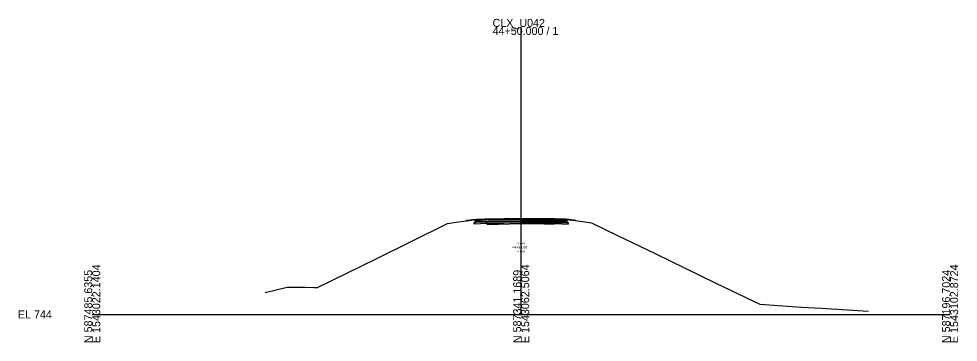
# Model space of a CAD drawing. Extents: x -26 to 1603, y -10 to 5557.
# Drawn here: x -25.7 to 302.8, y 990.3 to 1103.4 of the extents above; entities that cross this region are included whole.
import ezdxf

# ---------------------------------------------------------------- set-up
doc = ezdxf.new("R2010")
doc.units = 0
for name, color, linetype in [('GK_Cells', 7, 'Continuous'), ('XS_P_Annotation', 7, 'Continuous'), ('XS_P_Earthwork_Shapes', 7, 'Continuous'), ('XS_P_Finished_Grade', 7, 'Continuous'), ('XS_P_Pavt_Layers', 7, 'Continuous'), ('XS_P_Pavt_Surface', 7, 'Continuous'), ('XS_P_Shoulder_Layers', 7, 'Continuous'), ('XS_P_Shoulder_Surface', 7, 'Continuous'), ('XS_P_Subgrade', 7, 'Continuous'), ('XS_X_Ground_Line', 7, 'Continuous'), ('XS_X_Pavt', 7, 'Continuous')]:
    doc.layers.add(name, color=color, linetype=linetype)

msp = doc.modelspace()

# ---------------------------------------------------------------- linework, layer by layer
at = {"layer": 'GK_Cells'}
for p, q in [((150, 1000), (150, 1100.52)), ((0, 1000), (150, 1000)), ((150, 1000), (300, 1000))]:
    msp.add_line(p, q, dxfattribs=at)
at = {"layer": 'XS_P_Earthwork_Shapes'}
for points in [[(131, 1032.89), (130.63, 1032.7), (133.61, 1033.1)], [(131, 1032.89), (130.63, 1032.7), (133.61, 1033.1)], [(131, 1032.89), (130.63, 1032.7), (133.61, 1033.1)], [(131, 1032.89), (130.63, 1032.7), (133.61, 1033.1)], [(137.94, 1031.79), (133.58, 1031.61), (133.58, 1032.11), (134.08, 1032.13), (134.08, 1032.89), (134.41, 1032.9), (134.41, 1033.17), (133.61, 1033.1), (134.46, 1033.22), (134.54, 1033.22), (134.54, 1032.47), (137.21, 1032.53), (137.94, 1032.55)], [(137.94, 1031.79), (133.58, 1031.61), (133.58, 1032.11), (134.08, 1032.13), (134.08, 1032.89), (134.41, 1032.9), (134.41, 1033.17), (133.61, 1033.1), (134.46, 1033.22), (134.54, 1033.22), (134.54, 1032.47), (137.21, 1032.53), (137.94, 1032.55)], [(137.94, 1031.79), (133.58, 1031.61), (133.58, 1032.11), (134.08, 1032.13), (134.08, 1032.89), (134.41, 1032.9), (134.41, 1033.17), (133.61, 1033.1), (134.46, 1033.22), (134.54, 1033.22), (134.54, 1032.47), (137.21, 1032.53), (137.94, 1032.55)], [(137.94, 1031.79), (133.58, 1031.61), (133.58, 1032.11), (134.08, 1032.13), (134.08, 1032.89), (134.41, 1032.9), (134.41, 1033.17), (133.61, 1033.1), (134.46, 1033.22), (134.54, 1033.22), (134.54, 1032.47), (137.21, 1032.53), (137.94, 1032.55)], [(134.54, 1033.22), (137.21, 1033.28), (138.45, 1033.31), (142.04, 1033.37), (149.93, 1033.51), (158.15, 1033.42), (161.66, 1033.38), (164.55, 1033.33), (165.48, 1033.32), (165.48, 1032.57), (164.55, 1032.58), (161.66, 1032.63), (161.49, 1032.63), (158.15, 1032.67), (149.93, 1032.76), (142.04, 1032.62), (138.45, 1032.56), (137.94, 1032.55), (137.21, 1032.53), (134.54, 1032.47)], [(134.54, 1033.22), (137.21, 1033.28), (138.45, 1033.31), (142.04, 1033.37), (149.93, 1033.51), (158.15, 1033.42), (161.66, 1033.38), (164.55, 1033.33), (165.48, 1033.32), (165.48, 1032.57), (164.55, 1032.58), (161.66, 1032.63), (161.49, 1032.63), (158.15, 1032.67), (149.93, 1032.76), (142.04, 1032.62), (138.45, 1032.56), (137.94, 1032.55), (137.21, 1032.53), (134.54, 1032.47)], [(158.15, 1032.67), (161.49, 1032.63), (161.66, 1032.63), (164.55, 1032.58), (165.48, 1032.57), (165.48, 1033.32), (164.55, 1033.33), (161.66, 1033.38), (158.15, 1033.42), (149.93, 1033.51), (142.04, 1033.37), (138.45, 1033.31), (137.21, 1033.28), (134.54, 1033.22), (134.54, 1032.47), (137.21, 1032.53), (137.94, 1032.55), (138.45, 1032.56), (142.04, 1032.62), (149.93, 1032.76)], [(134.54, 1033.22), (137.21, 1033.28), (138.45, 1033.31), (142.04, 1033.37), (149.93, 1033.51), (158.15, 1033.42), (161.66, 1033.38), (164.55, 1033.33), (165.48, 1033.32), (165.48, 1032.57), (164.55, 1032.58), (161.66, 1032.63), (161.49, 1032.63), (158.15, 1032.67), (149.93, 1032.76), (142.04, 1032.62), (138.45, 1032.56), (137.94, 1032.55), (137.21, 1032.53), (134.54, 1032.47)], [(161.49, 1031.8), (150, 1031.98), (138.04, 1031.79), (137.94, 1031.79), (137.94, 1032.55), (138.45, 1032.56), (142.04, 1032.62), (149.93, 1032.76), (158.15, 1032.67), (161.49, 1032.63)], [(158.15, 1032.67), (161.49, 1032.63), (161.49, 1031.8), (150, 1031.98), (138.04, 1031.79), (137.94, 1031.79), (137.94, 1032.55), (138.45, 1032.56), (142.04, 1032.62), (149.93, 1032.76)], [(158.15, 1032.67), (161.49, 1032.63), (161.49, 1031.8), (150, 1031.98), (138.04, 1031.79), (137.94, 1031.79), (137.94, 1032.55), (138.45, 1032.56), (142.04, 1032.62), (149.93, 1032.76)], [(161.49, 1031.8), (150, 1031.98), (138.04, 1031.79), (137.94, 1031.79), (137.94, 1032.55), (138.45, 1032.56), (142.04, 1032.62), (149.93, 1032.76), (158.15, 1032.67), (161.49, 1032.63)], [(165.59, 1033.17), (168.42, 1032.93), (165.68, 1033.31), (165.48, 1033.32), (165.48, 1032.57), (164.55, 1032.58), (161.66, 1032.63), (161.49, 1032.63), (161.49, 1031.8), (161.96, 1031.79), (166.42, 1031.61), (166.42, 1032.11), (165.92, 1032.13), (165.92, 1032.89), (165.59, 1032.9)], [(165.48, 1033.32), (165.68, 1033.31), (168.42, 1032.93), (165.59, 1033.17), (165.59, 1032.9), (165.92, 1032.89), (165.92, 1032.13), (166.42, 1032.11), (166.42, 1031.61), (161.96, 1031.79), (161.49, 1031.8), (161.49, 1032.63), (161.66, 1032.63), (164.55, 1032.58), (165.48, 1032.57)], [(165.59, 1033.17), (168.42, 1032.93), (165.68, 1033.31), (165.48, 1033.32), (165.48, 1032.57), (164.55, 1032.58), (161.66, 1032.63), (161.49, 1032.63), (161.49, 1031.8), (161.96, 1031.79), (166.42, 1031.61), (166.42, 1032.11), (165.92, 1032.13), (165.92, 1032.89), (165.59, 1032.9)], [(165.48, 1033.32), (165.68, 1033.31), (168.42, 1032.93), (165.59, 1033.17), (165.59, 1032.9), (165.92, 1032.89), (165.92, 1032.13), (166.42, 1032.11), (166.42, 1031.61), (161.96, 1031.79), (161.49, 1031.8), (161.49, 1032.63), (161.66, 1032.63), (164.55, 1032.58), (165.48, 1032.57)], [(169, 1032.89), (169.09, 1032.84), (168.42, 1032.93)], [(169, 1032.89), (169.09, 1032.84), (168.42, 1032.93)], [(169, 1032.89), (169.09, 1032.84), (168.42, 1032.93)], [(169, 1032.89), (169.09, 1032.84), (168.42, 1032.93)]]:
    msp.add_lwpolyline(points, close=True, dxfattribs=at)
at = {"layer": 'XS_P_Finished_Grade'}
for p, q in [((131, 1032.89), (130.63, 1032.7)), ((134.41, 1033.17), (131, 1032.89)), ((165.59, 1033.17), (169, 1032.89)), ((169, 1032.89), (169.09, 1032.84))]:
    msp.add_line(p, q, dxfattribs=at)
at = {"layer": 'XS_P_Pavt_Layers'}
for p, q in [((133.58, 1032.11), (133.58, 1031.61)), ((134.08, 1032.89), (134.08, 1032.13)), ((134.41, 1033.17), (134.41, 1032.9)), ((150, 1033.38), (138, 1033.19)), ((150, 1033.23), (138, 1033.04)), ((150.02, 1032.48), (138.02, 1032.29)), ((150.02, 1031.98), (138.02, 1031.79)), ((149.98, 1032.48), (161.98, 1032.29)), ((149.98, 1031.98), (161.98, 1031.79)), ((150, 1033.38), (162, 1033.19)), ((150, 1033.23), (162, 1033.04)), ((165.59, 1033.17), (165.59, 1032.9)), ((165.92, 1032.89), (165.92, 1032.13)), ((166.42, 1032.11), (166.42, 1031.61))]:
    msp.add_line(p, q, dxfattribs=at)
at = {"layer": 'XS_P_Pavt_Surface'}
for q in [(138, 1033.31), (162, 1033.31)]:
    msp.add_line((150, 1033.5), q, dxfattribs=at)
at = {"layer": 'XS_P_Shoulder_Layers'}
for p, q in [((138.04, 1032.29), (133.58, 1032.11)), ((138.06, 1031.79), (133.58, 1031.61)), ((138.01, 1033.04), (134.08, 1032.89)), ((138, 1033.19), (134.42, 1033.04)), ((161.94, 1031.79), (166.42, 1031.61)), ((161.96, 1032.29), (166.42, 1032.11)), ((161.99, 1033.04), (165.92, 1032.89)), ((162, 1033.19), (165.58, 1033.04))]:
    msp.add_line(p, q, dxfattribs=at)
at = {"layer": 'XS_P_Shoulder_Surface'}
for p, q in [((138, 1033.31), (134.41, 1033.17)), ((162, 1033.31), (165.59, 1033.17))]:
    msp.add_line(p, q, dxfattribs=at)
at = {"layer": 'XS_P_Subgrade'}
msp.add_lwpolyline([(165.59, 1033.17), (165.59, 1032.9), (165.92, 1032.89), (165.92, 1032.13), (166.42, 1032.11), (166.42, 1031.61), (161.96, 1031.79), (150, 1031.98), (138.04, 1031.79), (133.58, 1031.61), (133.58, 1032.11), (134.08, 1032.13), (134.08, 1032.89), (134.41, 1032.9), (134.41, 1033.17)], dxfattribs=at)
at = {"layer": 'XS_X_Ground_Line'}
msp.add_lwpolyline([(60.47, 1007.73), (68.18, 1009.52), (73.06, 1009.6), (74.41, 1009.55), (77.48, 1009.43), (78.81, 1009.38), (99.25, 1019.49), (124.19, 1031.82), (127.23, 1032.24), (134.46, 1033.22), (137.21, 1033.28), (138.45, 1033.31), (142.04, 1033.37), (149.93, 1033.51), (158.15, 1033.42), (161.66, 1033.38), (164.55, 1033.33), (165.68, 1033.31), (172.23, 1032.41), (174.61, 1032.07), (183.7, 1027.62), (196.81, 1021.28), (218.08, 1010.95), (233.41, 1003.58), (244.81, 1002.78), (248.05, 1002.59), (254.99, 1002.19), (258.57, 1001.98), (260.75, 1001.85), (262.21, 1001.77), (271.47, 1001.14)], dxfattribs=at)
at = {"layer": 'XS_X_Pavt'}
for p, q in [((134.54, 1033.22), (134.54, 1032.47)), ((134.54, 1032.47), (137.21, 1032.53)), ((137.21, 1032.53), (137.94, 1032.55)), ((137.94, 1032.55), (138.45, 1032.56)), ((137.94, 1032.55), (137.94, 1031.55)), ((138.45, 1032.56), (142.04, 1032.62)), ((138.45, 1031.56), (142.04, 1031.62)), ((142.04, 1032.62), (149.93, 1032.76)), ((142.04, 1031.62), (149.93, 1031.76)), ((149.93, 1032.76), (158.15, 1032.67)), ((149.93, 1031.76), (158.15, 1031.67)), ((158.15, 1032.67), (161.49, 1032.63)), ((158.15, 1031.67), (161.49, 1031.63)), ((161.49, 1032.63), (161.66, 1032.63)), ((161.49, 1032.63), (161.49, 1031.63)), ((161.66, 1032.63), (164.55, 1032.58)), ((164.55, 1032.58), (165.48, 1032.57)), ((165.48, 1033.32), (165.48, 1032.57)), ((137.94, 1031.55), (138.45, 1031.56))]:
    msp.add_line(p, q, dxfattribs=at)

# ---------------------------------------------------------------- texts
at = {"layer": 'GK_Cells'}
for s, p in [('44+50.000 / 1', (140, 1097.72)), ('CLX_U042', (140, 1100.52)), ('EL 744', (-26, 998.6))]:
    msp.add_text(s, height=2.8, dxfattribs=at).set_placement(p)
for s, p in [('N 587485.6355', (0, 990)), ('E 1543022.1404', (2.8, 990)), ('N 587341.1689', (150, 990)), ('E 1543062.5064', (152.8, 990)), ('N 587196.7024', (300, 990)), ('E 1543102.8724', (302.8, 990))]:
    msp.add_text(s, height=2.8, rotation=90, dxfattribs=at).set_placement(p)
at = {"layer": 'XS_P_Annotation'}
for s, height, p in [('777.50', 0.7, (148.3, 1024.55)), ('44+50.00', 0.9, (146.89, 1023.05)), ('777.50', 0.7, (148.3, 1021.75))]:
    msp.add_text(s, height=height, dxfattribs=at).set_placement(p)

doc.saveas('drawing.dxf')
